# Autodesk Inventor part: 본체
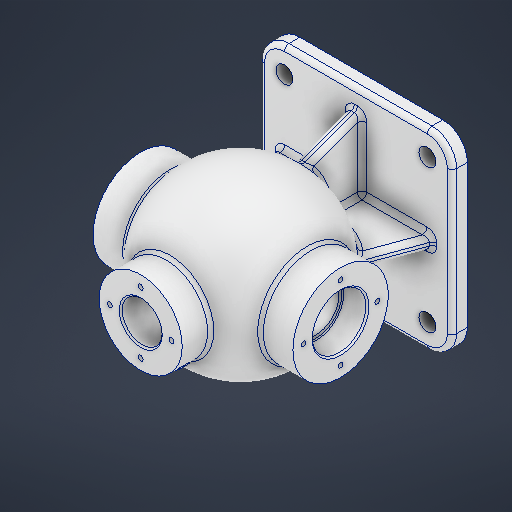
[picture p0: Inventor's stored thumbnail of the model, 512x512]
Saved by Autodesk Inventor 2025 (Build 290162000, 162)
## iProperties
Created: 2025-08
Part Number: 본체
Material: 알루미늄 6061
Document SubType Name: Modeling
Designer: infra027
Density: 2.7 g/cm^3
Appearance: 알루미늄 - 평지
Author: infra027
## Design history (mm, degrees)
sketch "스케치1"
  geometry: L1 (-62.5, -62.5)-(62.5, -62.5); L2 (62.5, -62.5)-(62.5, 62.5); L3 (62.5, 62.5)-(-62.5, 62.5); L4 (-62.5, 62.5)-(-62.5, -62.5); L5 (-62.5, -62.5)-(62.5, 62.5); L6 (62.5, -62.5)-(-62.5, 62.5); 1 further point
  constraints: 12 end point, 2 midpoint, 2 parallel, 1 horizontal, 1 perpendicular
  dimensions: "d0" = 125 distance of L3.end L2.end; "d1" = 125 distance of L2.end L1.end
extrude "돌출1" new body sketch "스케치1" stored distance "d2" = 10; taper "d3" = 0 deg
sketch "스케치2"
  geometry: L1 (-62.5, -5)-(62.5, -5) reference; L2 (54, 80)-(-54, 80); L3 (54, 80)-(162, 80); C1 r 54 at (0, 80); 4 further points
  constraints: 4 end point, 2 horizontal, 1 centre point, 1 coincident, 1 collinear, 1 midpoint
  dimensions: "d4" = 108 diameter of C1; "d5" = 0 horizontal distance of point (0, 0) C1.centre; "d6" = 85 distance from line of L1 C1.centre; "d7" = 108 distance of L2.start L2.end; "d8" = 180 deg angle of L2 L3 (derived)
revolve "회전1" sketch "스케치2" stored, may be unused: angle "d9" = 360 deg
sketch "스케치4"
  geometry: L1 (62.5, 5)-(130.065, 5); L2 (-62.5, 5)-(62.5, 5) reference; L3 (50.5, 5)-(31.217, 57.979); L4 (31.217, 57.979)-(-31.217, 57.979); L5 (-31.217, 57.979)-(-50.5, 5); L6 (62.5, -5)-(62.5, 5) reference; L7 (-62.5, -5)-(-62.5, 5) reference; 1 further point
  constraints: 8 end point, 2 point on line, 1 horizontal, 1 parallel
  dimensions: "d16" = 12 distance of L3.start L1.start; "d17" = 12 distance of L2.start L5.end; "d18" = 20 deg angle of L6 L3; "d19" = 20 deg angle of L7 L5; "d20" = 62.43455 distance of L3.end L4.end
extrude "돌출2" join sketch "스케치4" stored distance "d21" = 8; taper "d22" = 0 deg
sketch "스케치5"
  geometry: L1 (-62.5, 5)-(62.5, 5) reference; L2 (50.5, 5)-(28.797, 64.628); L3 (28.797, 64.628)-(-28.797, 64.628); L4 (4, 41.186)-(4, 5) reference; L5 (-28.797, 64.628)-(-50.5, 5); L6 (62.5, -5)-(62.5, 5) reference; L7 (-62.5, 5)-(-62.5, -5) reference; 3 further points
  constraints: 6 end point, 1 midpoint, 1 perpendicular, 1 point on line, 1 vertical alignment
  dimensions: "d23" = 12 distance of L1.end L2.start; "d24" = 12 distance of L1.start L5.end; "d25" = 20 deg angle of L6 L2; "d26" = 20 deg angle of L5 L7; "d27" = 57.59438 distance of L2.end L3.end
extrude "돌출3" join sketch "스케치5" stored distance "d28" = 8; taper "d29" = 0 deg
sketch "스케치6"
  geometry: L1 (-65, 111)-(65, 111); L2 (65, 111)-(65, 80); L3 (65, 80)-(-65, 80); L4 (-65, 80)-(-65, 111); L5 (62.5, -5)-(-62.5, -5) reference; L6 (-62.5, 5)-(62.5, 5) reference; 3 further points
  constraints: 8 end point, 2 midpoint, 2 parallel, 1 horizontal, 1 perpendicular, 1 vertical alignment
  dimensions: "d30" = 130 distance of L2.end L3.end; "d31" = 31 distance of L1.end L2.end; "d32" = 85 distance between parallel lines of L3 L5
revolve "회전2" sketch "스케치6" stored, may be unused: angle "d33" = 90 deg
sketch "스케치7"
  geometry: L1 (0, 145)-(27, 145); L2 (27, 145)-(27, 80); L3 (27, 80)-(0, 80); L4 (0, 80)-(0, 145); L5 (-62.5, 5)-(62.5, 5) reference; L6 (62.5, -5)-(-62.5, -5) reference; 2 further points
  constraints: 8 end point, 2 parallel, 1 horizontal, 1 midpoint, 1 perpendicular, 1 point on line
  dimensions: "d34" = 27 distance of L2.end L3.end; "d35" = 65 distance of L1.end L2.end; "d36" = 150 distance between parallel lines of L6 L1
revolve "회전3" sketch "스케치7" stored, may be unused: angle "d37" = 90 deg
sketch "스케치8"
  geometry: L1 (-44, 80)-(44, 80); L2 (-44, 80)-(44, 80); L3 (-62.5, 5)-(62.5, 5) reference; L4 (62.5, -5)-(-62.5, -5) reference; C1 r 44 at (0, 80); 6 further points
  constraints: 4 end point, 3 midpoint, 2 horizontal, 1 centre point, 1 coincident, 1 collinear, 1 vertical alignment
  dimensions: "d38" = 88 diameter of C1; "d39" = 88 distance of L1.start L1.end; "d40" = 0 distance between parallel lines of L1 L2 (derived); "d41" = 85 distance from line of L4 C1.centre
revolve "회전4" sketch "스케치8" stored, may be unused: angle "d42" = 360 deg
sketch "스케치9"
  geometry: C1 r 13 at (0, 0); C2 r 27 at (0, 0) reference; 1 further point
  constraints: 1 centre point, 1 concentric
  dimensions: "d43" = 26 diameter of C1
extrude "돌출4" cut sketch "스케치9" distance "d44" = 65; taper "d45" = 0 deg
sketch "스케치10"
  geometry: C1 r 15 at (0, 0); C2 r 31 at (0, 0) reference; 1 further point
  constraints: 1 centre point, 1 concentric
  dimensions: "d46" = 30 diameter of C1
extrude "돌출5" cut sketch "스케치10" extent not by distance; stored distance "d47" = 0; taper "d48" = 0 deg
sketch "스케치11"
  geometry: C1 r 17.5 at (0, 0); C2 r 31 at (0, 0) reference; 1 further point
  constraints: 1 centre point, 1 concentric
  dimensions: "d49" = 35 diameter of C1
extrude "돌출6" cut sketch "스케치11" distance "d50" = 16; taper "d51" = 0 deg
sketch "스케치12"
  geometry: C1 r 17.5 at (0, 0); C2 r 31 at (0, 0) reference; 1 further point
  constraints: 1 centre point, 1 concentric
  dimensions: "d52" = 35 diameter of C1
extrude "돌출7" cut sketch "스케치12" distance "d53" = 16; taper "d54" = 0 deg
sketch "스케치13"
  geometry: L1 (0, 0)-(24, 0); L2 (0, 0)-(24, 0); L3 (0, 0)-(0, 24); L4 (0, 0)-(0, 24); L5 (0, 0)-(-24, 0); L6 (0, 0)-(-24, 0); L7 (0, 0)-(0, -24); L8 (0, 0)-(0, -24); C1 r 24 at (0, 0); C2 r 31 at (0, 0) reference; C3 r 15 at (0, 0) reference; C4 r 24 at (0, 0); C5 r 24 at (0, 0); C6 r 24 at (0, 0); 11 further points
  constraints: 16 end point, 6 coincident, 4 centre point, 2 horizontal, 1 collinear, 1 concentric, 39 other
  dimensions: "d62" = 48 diameter of C1; "d63" = 24 distance of L1.start L1.end; "d64" = 0 distance between parallel lines of L1 L2 (derived); "d67" = 360 deg dimension on C1.centre point (-80, 0) (derived)
hole "구멍1" sketch "스케치13" at (24, 0), (0, 24), (-24, 0), (0, -24) diameter "d55" = 3.242; stored, may be unused: countersink angle "d59" = 90 deg, drill point angle "d61" = 118 deg; dims "d56" = 12, "d57" = 4, "d58" = 2, "d60" = 15
sketch "스케치14"
  geometry: L1 (0, 0)-(0, 20); L2 (0, 0)-(20, 0); L3 (0, 0)-(-20, 0); L4 (0, 0)-(0, 20); L5 (0, 0)-(0, -20); L6 (0, 0)-(-20, 0); L7 (0, 0)-(20, 0); L8 (0, 0)-(0, -20); C1 r 20 at (0, 0); C2 r 20 at (0, 0); C3 r 20 at (0, 0); C4 r 20 at (0, 0); 8 further points
  constraints: 16 end point, 10 coincident, 4 centre point, 1 horizontal, 1 perpendicular, 1 vertical, 31 other
  dimensions: "d76" = 40 diameter of C1; "d77" = 20 distance of L1.start L1.end; "d78" = 90 deg angle of L2 L1 (derived); "d81" = 360 deg dimension on point (0, 0) L1.end (derived)
hole "구멍2" sketch "스케치14" at (0, 20), (-20, 0), (0, -20), (20, 0) diameter "d69" = 3.242; stored, may be unused: countersink angle "d73" = 90 deg, drill point angle "d75" = 118 deg; dims "d70" = 9, "d71" = 4, "d72" = 2, "d74" = 11
chamfer "모따기1" distance "d83" = 1; stored, may be unused: second distance "d84" = 2, angle "d85" = 45 deg
chamfer "모따기2" distance "d86" = 1; stored, may be unused: second distance "d87" = 2, angle "d88" = 45 deg
chamfer "모따기3" distance "d89" = 1; stored, may be unused: second distance "d90" = 2, angle "d91" = 45 deg
fillet "모깎기1" dims "d92" = 3
fillet "모깎기2" dims "d93" = 16
fillet "모깎기3" dims "d94" = 3
fillet "모깎기4" dims "d95" = 3
fillet "모깎기5" dims "d96" = 3
fillet "모깎기6" dims "d97" = 3
sketch "스케치15"
  geometry: L1 (46.5, 46.5)-(-46.5, 46.5); L2 (-46.5, 46.5)-(-46.5, -46.5); L3 (-46.5, -46.5)-(46.5, -46.5); L4 (46.5, -46.5)-(46.5, 46.5); L5 (46.5, 46.5)-(-46.5, -46.5); L6 (-46.5, 46.5)-(46.5, -46.5); 5 further points
  constraints: 12 end point, 4 coincident, 2 midpoint, 2 parallel, 1 horizontal, 1 perpendicular
  dimensions: "d105" = 93 distance of L3.end L2.end; "d106" = 93 distance of L2.end L1.end
hole "구멍3" sketch "스케치15" at (-46.5, -46.5), (46.5, -46.5), (46.5, 46.5), (-46.5, 46.5) diameter "d98" = 11; stored, may be unused: countersink angle "d102" = 90 deg, drill point angle "d104" = 118 deg; dims "d99" = 9, "d100" = 4, "d101" = 2, "d103" = 11
fillet "모깎기7" dims "d113" = 0.6
node "작업 평면1"
sketch "스케치16" dims "d0" = 125, "d1" = 125
  geometry: L1 (18.056, 147.004)-(74.944, 147.004); L2 (74.944, 147.004)-(74.944, 134.996); L3 (74.944, 134.996)-(18.056, 134.996); L4 (18.056, 134.996)-(18.056, 147.004); L5 (73.5, 150)-(19.5, 150) reference; L6 (0, 0)-(93, 0) reference; 4 further points
  constraints: 3 midpoint, 1 vertical alignment, 2 other
  dimensions: "d116" = 134.99593 distance between parallel lines of L3 L6; "d117" = 56.88885 distance between parallel lines of L2 L4; "d124" = 9 distance from line of L5 point (74.944, 141)
feature "엠보싱3" sketch "스케치16" dims "d0" = 125, "d1" = 125, "d122" = 0.5, "d123" = 0
feature "Җ耀Ҙ耀Қ耀Ҝ耀Ҟ耀Ҡ耀Ң耀Ҥ耀" dims "d0" = 125, "d1" = 125, "d2" = 10, "d3" = 0, "d4" = 108, "d5" = 0, "d6" = 85, "d7" = 108, "d8" = 180 deg (derived), "d9" = 360 deg, "d16" = 12, "d17" = 12, "d18" = 20 deg, "d19" = 20 deg, "d20" = 62.43455, "d21" = 8, "d22" = 0, "d23" = 12, "d24" = 12, "d25" = 20 deg, "d26" = 20 deg, "d27" = 57.59438, "d28" = 8, "d29" = 0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
node "솔리드1"
mirror "미러1"
node "스케치 - 원형 패턴1" dims "d67" = 360 deg (derived)
node "스케치 - 원형 패턴2" dims "d81" = 360 deg (derived)
feature "A9D066F2-1C7D-4E18-AEED-F7BC21143FA4" dims "d98" = 11, "d99" = 9, "d100" = 4, "d101" = 2, "d102" = 90 deg, "d103" = 11, "d104" = 118 deg
